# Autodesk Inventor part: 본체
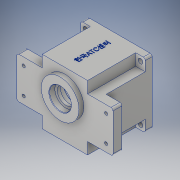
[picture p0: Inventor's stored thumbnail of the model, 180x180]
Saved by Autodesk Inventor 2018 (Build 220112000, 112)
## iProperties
Created: 2020-07
Part Number: 본체
Material: 알루미늄 6061
Document SubType Name: Modeling
Designer: Admin
Density: 2.7 g/cm^3
Appearance: 알루미늄 - 평지
Mass: 876.371 g
Surface Area: 793.906 cm^2
Volume: 324.582 cm^3
Author: Admin
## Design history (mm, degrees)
sketch "스케치1"
  geometry: L1 (-47, -47)-(47, -47); L2 (47, -47)-(47, 47); L3 (47, 47)-(-47, 47); L4 (-47, 47)-(-47, -47); L5 (-47, -47)-(47, 47); L6 (47, -47)-(-47, 47); 1 further point
  constraints: 12 end point, 2 midpoint, 2 parallel, 1 horizontal, 1 perpendicular
  dimensions: "d0" = 94 distance of L2.end L3.end; "d1" = 94 distance of L3.end L1.start
extrude "돌출1" new body sketch "스케치1" distance "d2" = 80; taper "d3" = 0 deg
sketch "스케치2"
  geometry: L1 (-70, -30)-(70, -30); L2 (70, -30)-(70, 30); L3 (70, 30)-(-70, 30); L4 (-70, 30)-(-70, -30); L5 (-70, -30)-(70, 30); L6 (70, -30)-(-70, 30); 1 further point
  constraints: 12 end point, 2 midpoint, 2 parallel, 1 horizontal, 1 perpendicular
  dimensions: "d4" = 140 distance of L2.end L3.end; "d5" = 60 distance of L1.end L2.end
extrude "돌출2" join sketch "스케치2" distance "d6" = 13; taper "d7" = 0 deg
sketch "스케치3"
  geometry: L1 (47, 30)-(47, 47) reference; L2 (47, 47)-(-47, 47) reference; L3 (-47, 47)-(-47, 30) reference; L4 (-47, 30)-(-70, 30) reference; L5 (-70, 30)-(-70, -30) reference; L6 (-70, -30)-(-47, -30) reference; L7 (-47, -30)-(-47, -47) reference; L8 (-47, -47)-(47, -47) reference; L9 (47, -47)-(47, -30) reference; L10 (47, -30)-(70, -30) reference; L11 (70, -30)-(70, 30) reference; L12 (70, 30)-(47, 30) reference; L13 (47, 47)-(-47, 47) reference; L14 (-47, 47)-(-33, 47); L15 (-33, 47)-(-33, 30); L16 (-33, 30)-(-47, 30); L17 (-47, 30)-(-47, 47); L18 (47, 47)-(33, 47); L19 (33, 47)-(33, 30); L20 (33, 30)-(47, 30); L21 (47, 30)-(47, 47); L22 (47, -47)-(47, 47) reference; L23 (47, -47)-(33, -47); L24 (33, -47)-(33, -30); L25 (33, -30)-(47, -30); L26 (47, -30)-(47, -47); L27 (-47, -47)-(47, -47) reference; L28 (-47, -47)-(-33, -47); L29 (-33, -47)-(-33, -30); L30 (-33, -30)-(-47, -30); L31 (-47, -30)-(-47, -47); L32 (-98, 0)-(98, 0) reference; L33 (0, -65.8)-(0, 65.8) reference; 1 further point
  constraints: 32 end point, 8 parallel, 4 horizontal, 4 perpendicular, 2 collinear, 4 other
  dimensions: "d8" = 66 distance between parallel lines of L19 L15; "d10" = 60 distance between parallel lines of L25 L20
extrude "돌출3" cut sketch "스케치3" distance "d11" = 70; taper "d12" = 0 deg
sketch "스케치4"
  geometry: L1 (0, -65.8)-(0, 65.8) reference; C1 r 27.5 at (0, 11); 1 further point
  constraints: 1 centre point, 1 point on line
  dimensions: "d13" = 11 distance of point (0, 0) C1.centre; "d14" = 55 diameter of C1
extrude "돌출4" join sketch "스케치4" distance "d15" = 7; taper "d16" = 0 deg
sketch "스케치5"
  geometry: C1 r 43 at (0, 0); 1 further point
  constraints: 1 centre point, 1 coincident
  dimensions: "d17" = 86 diameter of C1
extrude "돌출5" cut sketch "스케치5" distance "d18" = 9; taper "d19" = 0 deg
sketch "스케치6"
  geometry: C1 r 43 at (0, 0) reference; C2 r 40 at (0, 0); 1 further point
  constraints: 1 centre point, 1 coincident
  dimensions: "d20" = 80 diameter of C2
extrude "돌출6" cut sketch "스케치6" distance "d21" = 62; taper "d22" = 0 deg
sketch "스케치7"
  geometry: L1 (0, -65.8)-(0, 65.8) reference; C1 r 27.5 at (0, 11) reference; A1 r 15 centre (0, -20) between (-8.978, -7.984) and (8.978, -7.984); A2 r 21 centre (0, 11) between (8.978, -7.984) and (-8.978, -7.984); 1 further point
  constraints: 4 point on circle, 2 centre point, 1 coincident, 1 point on line
  dimensions: "d23" = 20 distance of point (0, 0) A1.centre; "d24" = 42 diameter of A2; "d25" = 30 diameter of A1
extrude "돌출7" join sketch "스케치7" distance "d26" = 7; taper "d27" = 0 deg
sketch "스케치8"
  geometry: C1 r 17.5 at (0, 11); A1 r 21 centre (0, 11) between (8.978, -7.984) and (-8.978, -7.984) reference; 1 further point
  constraints: 1 centre point, 1 coincident
  dimensions: "d28" = 35 diameter of C1
extrude "돌출8" cut sketch "스케치8" distance "d29" = 10; taper "d30" = 0 deg
sketch "스케치9"
  geometry: C1 r 27.5 at (0, 0) reference; C2 r 16 at (0, 0); 1 further point
  constraints: 1 centre point, 1 coincident
  dimensions: "d31" = 32 diameter of C2
extrude "돌출9" cut sketch "스케치9" distance "d32" = 8.3; taper "d33" = 0 deg
sketch "스케치10"
  geometry: C1 r 16 at (0, 0) reference; C2 r 12.5 at (0, 0); 1 further point
  constraints: 1 centre point, 1 coincident
  dimensions: "d34" = 25 diameter of C2
extrude "돌출10" cut sketch "스케치10" stored distance "d35" = 8.3; taper "d36" = 0 deg
sketch "스케치11"
  geometry: C1 r 11 at (0, -20); A1 r 15 centre (0, -20) between (-8.978, -7.984) and (8.978, -7.984) reference; 1 further point
  constraints: 1 centre point, 1 coincident
  dimensions: "d37" = 22 diameter of C1
extrude "돌출11" cut sketch "스케치11" distance "d38" = 7; taper "d39" = 0 deg
sketch "스케치12"
  geometry: C1 r 11 at (0, 0) reference; C2 r 9.5 at (0, 0); 1 further point
  constraints: 1 centre point, 1 coincident
  dimensions: "d40" = 19 diameter of C2
extrude "돌출12" cut sketch "스케치12" distance "d41" = 3; taper "d42" = 0 deg
sketch "스케치13" dims "d43" = 72
  geometry: L1 (98, 0)-(-98, 0) reference; L2 (0, -65.8)-(0, 65.8) reference; L3 (-36, 4)-(-36.332, 4); L4 (-36, 4)-(-39.799, 4); L5 (-36, -4)-(-39.799, -4); L6 (36, 4)-(36.332, 4); L7 (36, 4)-(39.799, 4); L8 (36, -4)-(39.799, -4); A1 r 40 centre (0, 0) between (-39.799, 4) and (-39.799, -4) reference; A2 r 4 centre (-36, 0) between (-36, -4) and (-36, 4); A3 r 40 centre (0, 0) between (-39.799, 4) and (-39.799, -4); A4 r 4 centre (36, 0) between (36, 4) and (36, -4); A5 r 40 centre (0, 0) between (39.799, -4) and (39.799, 4); 2 further points
  constraints: 12 end point, 10 point on circle, 6 symmetric about line, 4 centre point, 3 tangent, 2 coincident, 2 horizontal, 1 horizontal alignment, 1 parallel, 1 point on line, 4 other
  dimensions: "d44" = 8 diameter of A2
extrude "돌출13" join sketch "스케치13" stored distance "d47" = 0; taper "d48" = 0 deg
chamfer "모따기1" distance "d49" = 1; stored, may be unused: second distance "d50" = 2, angle "d51" = 45 deg
chamfer "모따기2" distance "d52" = 0.8; stored, may be unused: second distance "d53" = 2, angle "d54" = 30 deg
fillet "모깎기1" dims "d55" = 3
fillet "모깎기2" dims "d56" = 3
sketch "스케치14"
  geometry: L1 (33, 97.4)-(33, -24.4) reference; L2 (77, 80)-(-11, 80) reference; 2 further points
  constraints: 1 point on line, 1 other
  dimensions: "d57" = 40 distance from line of point (33, 40) L2
feature "엠보싱1" sketch "스케치14" dims "d0" = 94, "d1" = 94, "d58" = 0.5, "d59" = 0
fillet "모깎기3" dims "d60" = 3
sketch "스케치15"
  geometry: L1 (98, 0)-(-98, 0) reference; L2 (0, -65.9)-(0, 66.4) reference; 5 further points
  constraints: 4 symmetric about line
  dimensions: "d61" = 120 distance of point (-60, 19) point (60, 19); "d62" = 38 distance of point (60, -19) point (60, 19)
hole "구멍1" sketch "스케치15" at (-60, 19), (60, 19), (60, -19), (-60, -19) diameter "d63" = 4.5; stored, may be unused: countersink angle "d67" = 90 deg, drill point angle "d69" = 118 deg; dims "d64" = 6, "d65" = 10, "d66" = 5, "d68" = 8
sketch "스케치16"
  geometry: L1 (98, 0)-(-98, 0) reference; L2 (0, -65.9)-(0, 66.4) reference; 5 further points
  constraints: 4 symmetric about line
  dimensions: "d70" = 80 distance of point (40, 40) point (-40, 40); "d71" = 80 distance of point (40, -40) point (40, 40)
hole "구멍2" sketch "스케치16" at (-40, 40), (40, 40), (40, -40), (-40, -40) diameter "d72" = 7; stored, may be unused: countersink angle "d76" = 90 deg, drill point angle "d78" = 118 deg; dims "d73" = 6, "d74" = 10, "d75" = 5, "d77" = 10
sketch "스케치17"
  geometry: A1 r 4 centre (-36, 0) between (-36, -4) and (-36, 4) reference; A2 r 4 centre (36, 0) between (36, 4) and (36, -4) reference; 3 further points
  constraints: 2 coincident
hole "구멍3" sketch "스케치17" at (-36, 0), (36, 0) diameter "d79" = 3.242; stored, may be unused: countersink angle "d83" = 90 deg, drill point angle "d85" = 118 deg; dims "d80" = 7, "d81" = 10, "d82" = 5, "d84" = 9
node "솔리드1"
node "투영된 루프1"
